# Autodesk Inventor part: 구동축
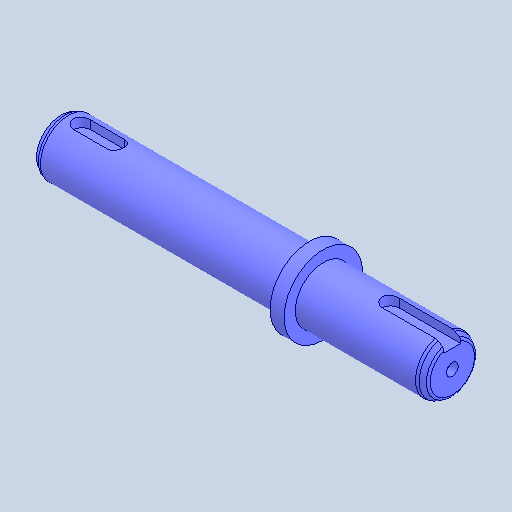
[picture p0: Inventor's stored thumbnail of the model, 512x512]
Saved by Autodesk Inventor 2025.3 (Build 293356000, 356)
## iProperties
Created: 2026-01
Part Number: 구동축
Material: 강철, 탄소
Document SubType Name: Modeling
Designer: PC-13
Density: 7.85 g/cm^3
Appearance: 기본값
Author: jhkim
Sending System: Autodesk Inventor 2026
Preprocessor: ST-DEVELOPER v20.1
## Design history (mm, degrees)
feature "솔리드1"
node "솔리드2"
